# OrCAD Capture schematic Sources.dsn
size A
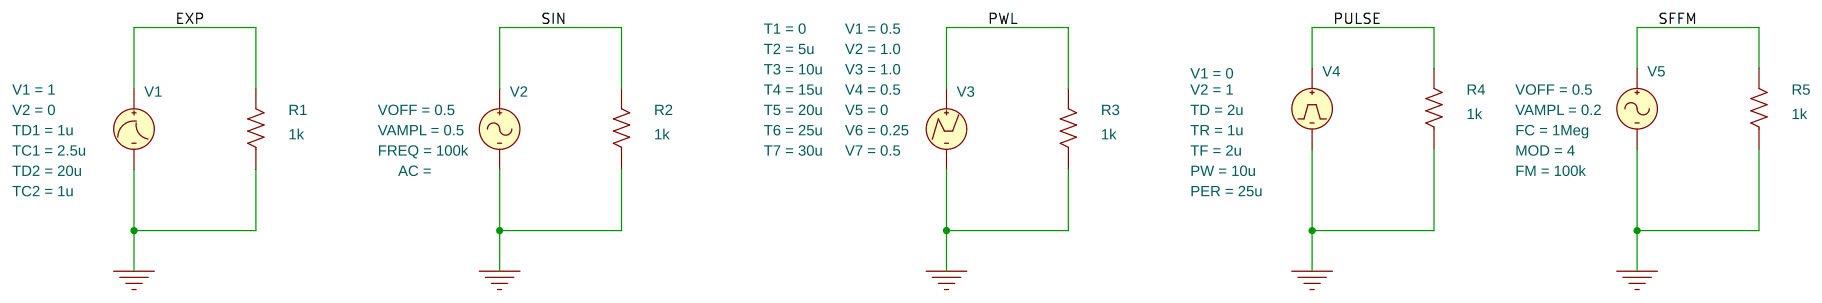
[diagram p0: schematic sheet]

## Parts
R1  1k  [AXRC05]
R2  1k  [AXRC05]
R3  1k  [AXRC05]
R4  1k  [AXRC05]
R5  1k  [AXRC05]
V1  VEXP
V2  VSIN
V3  VPWL
V4  VPULSE
V5  VSFFM

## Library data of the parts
R1-R5 = R
V1 = VEXP: TC1: 2.5u; TC2: 1u; TD1: 1u; TD2: 20u; V1: 1; V2: 0
V2 = VSIN: FREQ: 100k; VAMPL: 0.5; VOFF: 0.5
V3 = VPWL: T1: 0; T2: 5u; T3: 10u; T4: 15u; T5: 20u; T6: 25u; T7: 30u; V1: 0.5; V2: 1.0; V3: 1.0; V4: 0.5; V5: 0; V6: 0.25; V7: 0.5
V4 = VPULSE: PER: 25u; PW: 10u; TD: 2u; TF: 2u; TR: 1u; V1: 0; V2: 1
V5 = VSFFM: FC: 1Meg; FM: 100k; MOD: 4; VAMPL: 0.2; VOFF: 0.5

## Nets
0: R1.1 R2.1 R3.1 R4.1 R5.1 V1.2(-) V2.2(-) V3.2(-) V4.2(-) V5.2(-)
EXP: R1.2 V1.1(+)
PULSE: R4.2 V4.1(+)
PWL: R3.2 V3.1(+)
SFFM: R5.2 V5.1(+)
SIN: R2.2 V2.1(+)
